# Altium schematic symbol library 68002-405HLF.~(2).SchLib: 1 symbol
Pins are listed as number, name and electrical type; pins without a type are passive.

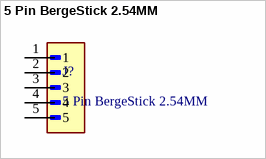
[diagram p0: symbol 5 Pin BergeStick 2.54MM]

## 5 Pin BergeStick 2.54MM
designator J?
5 Pin 5Pos THT BergeStick 2.54MM Amphenol68002-405HLF 3A
footprint AMPHENOL_68002-405HLF
pins: 1, 2, 3, 4, 5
